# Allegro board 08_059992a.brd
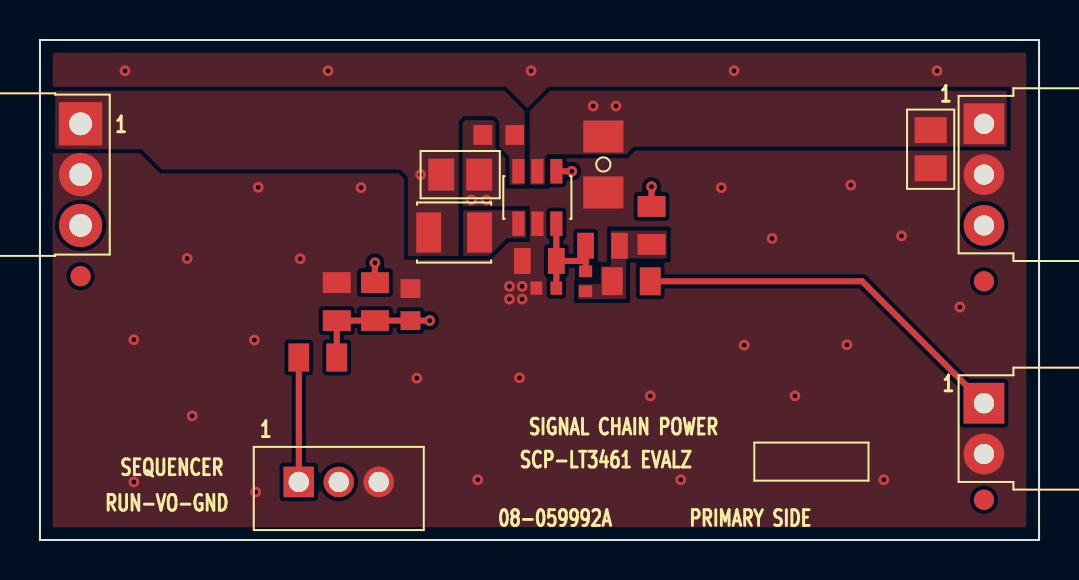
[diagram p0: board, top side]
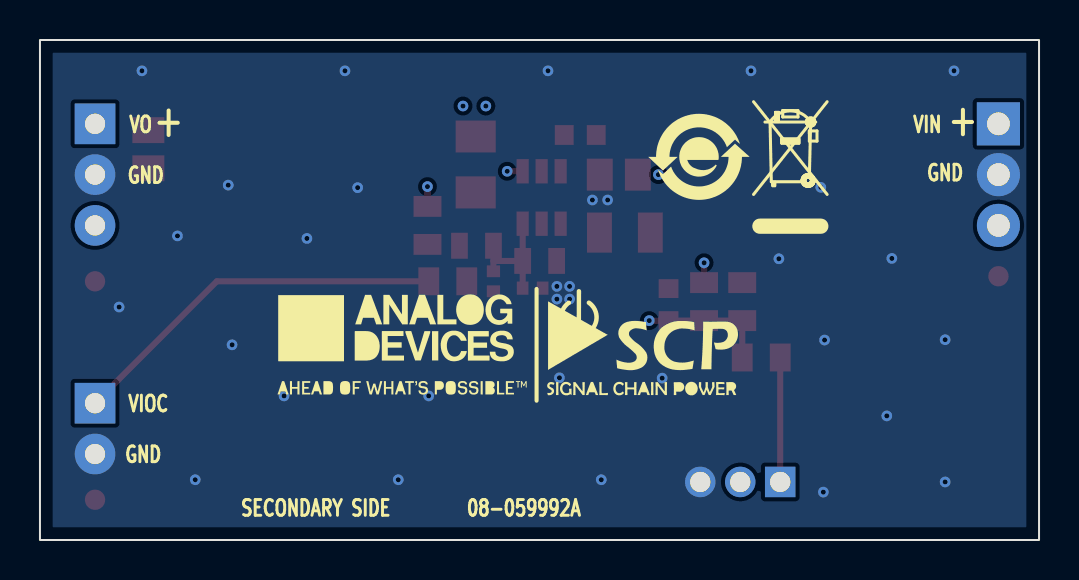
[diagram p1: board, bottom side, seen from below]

Outline 50 x 25 mm; copper layers: TOP, L2, L3, BOTTOM. Coordinates in mm from the lower left corner of the outline.
Outline path: rectangle 0,0 50,25

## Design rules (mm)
constraint set DEFAULT: min track width 0.203

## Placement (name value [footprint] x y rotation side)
C1  0.1UF  [C0603]  22.96 20.25 0 top
C2  4.7UF  [C0805H53]  21.03 18.27 180 top
C3  1.0UF  [C1206H71]  28.19 18.78 90 top
C4  0.47UF  [C0805H53]  44.58 19.54 90 top
C5  22PF  [C0402]  27.3 12.94 270 top
C6  0.047UF  [C0603]  18.54 11.77 90 top
C7  TBD0402  [C0402]  25.34 12.59 0 top
INPUT  PBC03SBAN  [CNTHMHDRRA1X3L300W100H145]  2.03 20.81 270 top
L1  15UH  [L1210H67]  20.73 15.37 0 top
NOREF  -  []  25.51 46.03 0 top
NOREF#2  -  []  -236.47 -197.38 0 top
NOREF#3  -  []  -196.72 -198.27 0 top
NOREF#4  -  []  50 0 90 top
NOREF#5  -  []  -124.49 -42.06 0 top
NOREF#6  -  []  -0.02 -0.07 0 top
NOREF#7  -  [unnamed#2]  47.24 2.01 0 top
NOREF#8  -  []  -115.76 170.77 0 top
NOREF#9  -  []  74.42 124.31 0 top
NOREF#10  -  []  -0.02 25.07 270 top
NOREF#11  -  []  50.02 25.07 180 top
NOREF#12  -  []  0 0 0 top
NOREF#13  -  [unnamed#2]  47.24 12.94 0 top
NOREF#14  -  [unnamed#2]  2.03 13.19 0 top
NOREF#15  -  []  -349.65 -285.95 0 top
NOREF#16  -  []  50.02 -0.07 90 top
NOREF#17  -  []  19.81 9.89 180 bottom
NOREF#18  -  []  17.02 19.16 180 bottom
NOREF#19  -  []  12.65 15.37 180 bottom
NOREF#20  -  []  32.17 9.74 180 bottom
OUTPUT  PPPC031LGBN-RC  [CNHDRRA1X3H108]  47.24 20.81 270 top
P1  53253-0370  [CNTHMHDR1X3L315W144H224]  12.95 2.9 0 top
R1  261K  [R0805#2]  28.15 14.71 0 top
R2  30.9K  [R0805#2]  24.99 13.95 0 top
R3  0  [R0805]  30.61 15.73 270 top
R4  0  [R0805]  16.76 11.92 270 top
R5  0  [R0805]  14.85 11.92 90 top
R6  0  [R0805]  13.9 9.13 0 top
R7  0  [R0805]  29.59 12.94 0 top
U1  LT3461ES6#PBF  [TSOT23_6]  24.89 17.13 0 top
VIOC  PPPC021LGBN-RC  [CNTHFHDRRA1X2L220W335H108]  47.24 6.84 270 top

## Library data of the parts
C1 = CAP: User Part Number: UPN; Tolerance: 10; alternate symbols: (); part number: CAP_SM-0.1UF,25V,10,E038719,C0603; tolerance: 10
C2 = CAP: Tolerance: 10; User Part Number: UPN; alternate symbols: (); part number: CAP_SM-4.7UF,25V,10,E034916,C0805H53; tolerance: 10
C3 = CAP: Tolerance: 10; User Part Number: UPN; alternate symbols: (); part number: CAP_SM-1.0UF,50V,10,E031061,C1206H71; tolerance: 10
C4 = CAP: Tolerance: 10; User Part Number: UPN; alternate symbols: (C0805L); part number: CAP_SM-0.47UF,50V,10,E041898,C0805H53; tolerance: 10
C5 = CAP: User Part Number: UPN; Tolerance: 5; alternate symbols: (); part number: CAP_SM-22PF,50V,5,E036085,C0402; tolerance: 5
C6 = CAP: User Part Number: UPN; Tolerance: 10; alternate symbols: (); part number: CAP_SM-0.047UF,16V,10,E028365,C0603; tolerance: 10
C7 = CAP: User Part Number: UPN; alternate symbols: (C0402L_ALT); part number: CAP_SM-TBD0402,TBD0402,TBD0402,E000381,C0402
INPUT = CN3P: Tolerance: N/A; User Part Number: UPN; alternate symbols: (CNTHMHDRRA1X3L300W100H145_SCP); part number: CN3P_TH-PBC03SBAN,E034137,CNTHMHDRRA1X3L300W100H145; tolerance: N/A
L1 = IND: User Part Number: UPN; Tolerance: 10; alternate symbols: (); part number: IND_SM-15UH,10,E033378,L1210H67; tolerance: 10
OUTPUT = CN3P: User Part Number: UPN; Tolerance: N/A; alternate symbols: (CNHDRRA1X3H108_SCP); part number: CN3P_TH-PPPC031LGBN-RC,E034111,CNHDRRA1X3H108; tolerance: N/A
P1 = CN3P: Tolerance: N/A; User Part Number: UPN; alternate symbols: (); part number: CN3P_TH-53253-0370,E033940,CNTHMHDR1X3L315W144H224; tolerance: N/A
R1 = RES: User Part Number: UPN; Tolerance: 1; alternate symbols: R0805L; part number: RES_SM-261K,E040458,1/8W,1,R0805; tolerance: 1
R2 = RES: User Part Number: UPN; Tolerance: 1; alternate symbols: R0805L; part number: RES_SM-30.9K,E040459,1/8W,1,R0805; tolerance: 1
R3-R7 = RES: User Part Number: UPN; Tolerance: N/A; alternate symbols: (R0805L); part number: RES_SM-0,E030875,1/8W,N/A,R0805; tolerance: N/A
U1 = ADLT3461: User Part Number: UPN; Tolerance: N/A; alternate symbols: (); part number: ADLT3461_SM-LT3461ES6#PBF,E040423,TSOT23_6; tolerance: N/A
VIOC = CN2P: Tolerance: N/A; User Part Number: UPN; alternate symbols: (CNTHFHDRRA1X2L220W335H108_SCP); part number: CN2P_TH-PPPC021LGBN-RC,E034113,CNTHFHDRRA1X2L220W335H108; tolerance: N/A

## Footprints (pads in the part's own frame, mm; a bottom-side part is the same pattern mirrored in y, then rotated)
C0402
  rect 0.584x0.66 smd: 1(-0.5,0) 2(0.5,0)
C0603
  rect 0.94x0.991 smd: 1(-0.8,0) 2(0.8,0)
C0805H53
  rect 1.295x1.6 smd: 1(-0.953,0) 2(0.953,0)
C1206H71
  rect 1.6x2.007 smd: 1(-1.397,0) 2(1.397,0)
CNHDRRA1X3H108
  rect 2.032x2.032 hole 1.016: 1(0,0)
  round 2.032 hole 1.016: 2(2.54,0) 3(5.08,0)
CNTHFHDRRA1X2L220W335H108
  rect 2.032x2.032 hole 1.016: 1(0,0)
  round 2.032 hole 1.016: 2(2.54,0)
CNTHMHDR1X3L315W144H224
  rect 1.524x1.524 hole 1.016: 1(0,0)
  round 1.524 hole 1.016: 2(2,0) 3(4,0)
CNTHMHDRRA1X3L300W100H145
  rect 2.159x2.159 hole 1.143: 1(0,0)
  round 2.159 hole 1.143: 2(2.54,0) 3(5.08,0)
L1210H67
  rect 1.245x2.007 smd: 1(-1.272,0) 2(1.272,0)
R0805
  rect 1.041x1.397 smd: 1(-0.95,0) 2(0.95,0)
R0805#2
  rect 0.838x1.295 smd: 1(-0.85,0) 2(0.85,0)
TSOT23_6
  rect 0.61x1.219 smd: 1(-0.95,-1.31) 2(0,-1.31) 3(0.95,-1.31) 4(0.95,1.31) 5(0,1.31) 6(-0.95,1.31)
unnamed#2
  round 1.016 smd: (0,0)

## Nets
AGND: C1.1 C2.1 C3.1 C4.1 C6.2(N2) C7.1 INPUT.2 OUTPUT.2 P1.3(N3) R2.1 R5.2(N2) U1.2 VIOC.2(N2)
VIN: C1.2(N2) C2.2(N2) INPUT.1 L1.1 R4.1 U1.6
RUN: P1.1 R6.1
SHDN_N: C6.1 R4.2(N2) R5.1 R6.2(N2) U1.4
UNNAMED_2_ADLT3461_I7_SW: L1.2(N2) U1.1
UNNAMED_2_CAP_I9_N2: C5.2(N2) R1.2(N2) R3.2(N2) R7.1
UNNAMED_2_CAP_I10_N2: C5.1 C7.2(N2) R1.1 R2.2(N2) U1.3
VIOC: R7.2(N2) VIOC.1
VO+: C3.2(N2) C4.2(N2) OUTPUT.1 P1.2 R3.1 U1.5(VOUT)

Pads without a net: INPUT 3; OUTPUT 3

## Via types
v1: diameter 0.533, hole 0.254, TOP to BOTTOM, 41 vias

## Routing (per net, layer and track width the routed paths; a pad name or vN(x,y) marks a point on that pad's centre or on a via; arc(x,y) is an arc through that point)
AGND:
  vias: v1(4.26,23.46) v1(4.7,10.01) v1(4.7,2.9) v1(7.37,14.08) v1(7.62,6.2) v1(10.73,10) v1(10.79,2.39) v1(10.92,17.63) v1(13.02,14.06) v1(14.42,23.46) v1(16.07,17.62) v1(18.86,8.09) v1(21.59,17) v1(21.91,3.01) v1(22.35,17) v1(23.5,12.68) v1(23.5,12.05) v1(24,8.11) v1(24.13,12.68) v1(24.13,12.05) v1(24.58,23.46) v1(30.55,7.2) v1(32.07,3.01) v1(34.1,17.62) v1(34.74,23.46) v1(35.24,9.74) v1(36.64,15.08) v1(37.78,7.2) v1(40.39,9.76) v1(40.58,17.74) v1(42.23,3.01) v1(43.12,15.2) v1(44.9,23.46) v1(46.04,11.65)
VIN: length 6.3
  TOP w0.305: R4.1 v1(16.76,13.86)
  L3 w0.305: v1(16.76,13.86) 19.05,16.15 v1(19.05,18.27)
RUN: length 6.2
  TOP w0.305: R6.1 P1.1
SHDN_N: length 21
  TOP w0.305: R6.2 R5.1 R4.2 C6.1 v1(19.51,10.97) ; U1.4 v1(26.62,18.44)
  L3 w0.305: v1(26.62,18.44) 26.62,12.37 25.21,10.97 v1(19.51,10.97)
UNNAMED_2_CAP_I10_N2: length 6
  TOP w0.305: 27.3,13.95 R2.2 ; 27.3,13.95 R1.1 ; 27.3,13.95 C5.1 ; R2.2 U1.3 ; R2.2 C7.2
VIOC: length 19.2
  TOP w0.305: VIOC.1 41.15,12.94 R7.2
VO+: length 35
  TOP w0.305: R3.1 v1(30.61,17.67)
  L3 w0.305: P1.2 17.24,5.19 26.04,5.19 27.69,6.84 v1(27.69,21.7) ; v1(28.83,21.7) 28.83,19.45 v1(30.61,17.67)

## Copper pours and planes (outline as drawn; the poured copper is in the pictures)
AGND on TOP, BOTTOM, L2, L3: 0.64,24.36 49.36,24.36 49.36,0.64 0.64,0.64
VIN on TOP: 0.76,22.46 23.24,22.46 24.26,21.44 24.26,17.76 23.5,17.76 23.5,19.16 22.99,19.67 22.99,20.94 22.73,21.19 21.21,21.19 20.95,20.94 20.95,14.21 18.41,14.21 18.41,18.14 18.03,18.52 6.1,18.52 5.08,19.54 0.76,19.54
UNNAMED_2_ADLT3461_I7_SW on TOP: 24.32,16.49 24.32,15.09 23.37,15.09 22.48,14.21 21.18,14.21 21.18,16.49
UNNAMED_2_CAP_I9_N2 on TOP: 28.57,15.48 31.37,15.48 31.37,14.08 29.34,14.08 29.34,12.05 26.92,12.05 26.92,12.81 28.07,12.81 28.07,13.7 28.57,13.7
VO+ on TOP: 25.53,22.46 48.39,22.46 48.39,19.67 29.72,19.67 29.34,19.29 25.4,19.29 25.27,19.16 25.27,17.76 24.51,17.76 24.51,21.44

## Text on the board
Ref Des/Silkscreen Bottom: GND | VIN | 08-059992A | SECONDARY SIDE | VIOC | VO | +
User.Comments: 4.    RoHS COMPLIANCE: ASSEMBLY VENDOR SHOULD ASSURE COMPLIANCE | WITH LEAD-FREE AND RoHS PCB ASSEMBLY STANDARDS (EU RoHS | DIRECTIVE 2002/95/EC).
Ref Des/Silkscreen Top: RUN-VO-GND | SEQUENCER | 08-059992A | SCP-LT3461 EVALZ | SIGNAL CHAIN POWER | PRIMARY SIDE
DIMENSION: REF | 0.165 | -0.819 | "0" | HOLE TOLERANCE | PLATED: +/- 3 MILS | UNLESS SPECIFIED | SEE FAB NOTE 15 | DIA MAX | -0.080 | 1.889
User.15: MATERIALS; | ENIG (Electroless Nickel/Immersion Gold) | PER IPC-4552 LATEST REVISION | HOMOGENOUS MATERIALS IN THIS BOARD SHALL BE COMPLIANT | THE EU RoHS DIRECTIVE 2002/95/EC | 15.    THRU VIAS TO BE FILLED WITH SOLDERMASK.
User.17: L2 | 08-      -07
User.18: L3 | 08-      -08
User.45: FIGURE | SIZE | 10.0 | 40.0 | 45.0 | PLATED | FINISHED HOLES IN MILS | ALL UNITS ARE IN MILS | QTY | 41 | 8 | 3 | TOLERANCE/NOTES
